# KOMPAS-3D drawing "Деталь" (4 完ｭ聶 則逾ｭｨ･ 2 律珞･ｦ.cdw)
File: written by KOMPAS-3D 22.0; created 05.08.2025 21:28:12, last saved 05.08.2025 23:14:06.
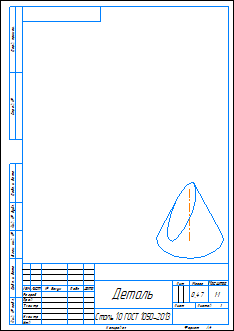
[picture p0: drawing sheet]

Sheet 1: A4, portrait

Document properties: Автор: user; Масса: 0.468006; Полное имя файла: G:\08 05 вторник\2025 НГ Лаб работы\Лаб 4 Сечение конуса\4 Чертежи\4 Конус Сечение 2 Чертеж.cdw

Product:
- Part/product: Деталь
    Масса: 0.494645

Title block, sheet 1: Наименование: Деталь; Материал: Сталь 10 ГОСТ 1050-2013; Масса: 0,47; Количество листов документа: 1; Форматы листов документа: A4; stored path: G:\08 05 вторник\2025 НГ Лаб работы\Лаб 4 Сечение конуса\4 Чертежи\4 Конус Сечение 4 Чертеж.cdw

Views: Изометрия 2
Dimensions and other numbers on the sheet: 1:1; 1; 0,47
